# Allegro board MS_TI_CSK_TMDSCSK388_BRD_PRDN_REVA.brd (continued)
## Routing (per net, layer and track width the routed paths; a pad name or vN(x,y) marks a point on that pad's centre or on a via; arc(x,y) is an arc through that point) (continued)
DM388_GMII_RXER: length 37.2
  TOP w0.102: v1(40.52,25.41) 41.02,25.41 41.48,24.95 U7.AJ2
  L06_SIG2 w0.102: 38.94,25.41 v1(40.52,25.41)
  L06_SIG2 w0.119: v1(18.9,27.83) 18.3,28.42 16.36,28.42 16.24,28.54 16.24,28.9 16.36,29.02 25.78,29.02 26.17,29.41 27.87,29.41 28.72,30.26 33.3,30.26 33.42,30.14 33.42,29.78 33.54,29.67 33.78,29.67 33.9,29.78 33.9,30.14 34.02,30.26 35.83,30.26 37.07,29.02 37.07,28.65 36.95,28.53 36.79,28.53 36.7,28.44 36.7,28.12 36.82,28 37.36,28 37.6,27.77 37.6,26.7 38.88,25.41 38.94,25.41
  BOTTOM w0.14: 16.97,28.33 18.4,28.33 18.4,28.32 v1(18.9,27.83)
DM388_GMII_TXD[0]: length 23.5
  TOP w0.14: RA2.5 30.27,27.19 29.96,26.88 29.96,25.95 v1(30.04,25.87)
  L06_SIG2 w0.119: v1(18.98,21.18) 19.55,21.18 19.87,21.51 19.87,25.36 19.99,25.48 22.64,25.48 22.76,25.6 22.76,25.94 22.88,26.06 23.12,26.06 23.24,25.94 23.24,25.6 23.36,25.48 23.6,25.48 23.72,25.6 23.72,25.94 23.83,26.06 24.07,26.06 24.19,25.94 24.19,25.6 24.31,25.48 24.55,25.48 24.67,25.6 24.67,25.94 24.79,26.06 25.03,26.06 25.15,25.94 25.15,25.6 25.27,25.48 25.51,25.48 25.63,25.6 25.63,25.94 25.74,26.06 25.98,26.06 26.1,25.94 26.1,25.6 26.22,25.48 26.46,25.48 26.58,25.6 26.58,25.94 26.7,26.06 29.85,26.06 v1(30.04,25.87)
  BOTTOM w0.14: v1(18.98,21.18) 18.53,21.18 18.39,21.33 J4.17
DM388_GMII_TXD[1]: length 22.8
  TOP w0.14: v1(30.39,26.42) 30.55,26.42 30.67,26.54 RA2.6
  L06_SIG2 w0.119: v1(17.87,20.85) 18.77,21.76 19.43,21.76 19.6,21.93 19.6,25.57 19.44,25.73 18.82,25.73 18.69,25.86 18.69,26.07 18.81,26.19 19.93,26.19 20.04,26.07 20.04,25.92 20.16,25.8 20.4,25.8 20.52,25.92 20.52,26.24 20.64,26.36 20.88,26.36 21,26.24 21,25.92 21.12,25.8 21.36,25.8 21.48,25.92 21.48,26.24 21.6,26.36 21.84,26.36 21.95,26.24 21.95,25.92 22.07,25.8 22.31,25.8 22.43,25.92 22.43,26.24 22.55,26.36 28.57,26.36 28.63,26.42 v1(30.39,26.42)
  BOTTOM w0.14: J4.15 17.68,20.83 17.71,20.85 v1(17.87,20.85)
DM388_GMII_TXD[2]: length 24.3
  TOP w0.14: RA2.7 30.81,26.04 30.44,25.66 v1(30.44,25.16)
  L06_SIG2 w0.119: v1(30.44,25.16) 29.83,25.16 29.78,25.21 29.43,25.21 29.31,25.32 29.31,25.68 29.16,25.82 28.95,25.82 28.83,25.7 28.83,25.32 28.71,25.21 28.47,25.21 28.35,25.32 28.35,25.71 28.23,25.83 28,25.83 27.88,25.71 27.88,25.32 27.76,25.21 27.52,25.21 27.4,25.32 27.4,25.72 27.28,25.84 27.05,25.84 26.92,25.7 26.92,25.32 26.8,25.21 20.34,25.21 20.18,25.04 20.18,21.38 19.18,20.38 19.01,20.38 18.78,20.6 18.61,20.6 18.44,20.44 18.44,20.27 18.67,20.04 18.67,19.87 18.31,19.5 17.56,19.5 17.44,19.62 17.44,20.03 17.55,20.14 v1(17.81,20.14)
  BOTTOM w0.14: J4.13 17.52,20.33 17.71,20.14 v1(17.81,20.14)
DM388_GMII_TXD[3]: length 21
  TOP w0.102: v1(26.95,23.5) 27.21,23.75
  TOP w0.14: RA2.8 31.07,24.85 30.73,24.51 27.97,24.51 27.21,23.75
  L03_SIG1 w0.119: v1(17.86,19.11) 20.08,19.11 20.2,19.23 20.2,19.45 20.08,19.57 19.23,19.57 19.11,19.69 19.11,19.93 19.23,20.05 20.05,20.05 20.2,20.2 20.2,21.76 20.58,22.14 20.58,22.57 21.82,23.81 26.64,23.81 v1(26.95,23.5)
  BOTTOM w0.14: J4.9 17.51,18.83 17.78,19.1 17.85,19.1 v1(17.86,19.11)
DM388_GMII_TXD[4]: length 25.9
  TOP w0.14: RA3.5 34.1,27.19 33.73,26.82 33.73,26.24 33.09,25.6 32.93,25.6 v1(32.61,25.28)
  L06_SIG2 w0.119: v1(32.61,25.28) 32.17,25.28 32.11,25.21 32.11,24.87 31.93,24.7 31.55,24.7 31.43,24.82 31.43,25.52 31.31,25.64 31.07,25.64 30.95,25.52 30.95,24.82 30.83,24.7 29.74,24.7 29.5,24.93 20.63,24.93 20.45,24.76 20.45,21.19 19.62,20.36 19.62,20.15 v1(17.87,18.4)
  BOTTOM w0.14: J4.7 17.8,18.33 v1(17.87,18.4)
DM388_GMII_TXD[5]: length 24.6
  TOP w0.14: RA3.6 34.19,26.54 34.02,26.38 34.02,26.1 33.62,25.7 33.62,25.51 v1(33.59,25.48)
  L06_SIG2 w0.119: v1(17.86,17.69) 18.82,18.65 18.99,18.65 19.2,18.44 19.37,18.44 19.54,18.61 19.54,18.77 19.33,18.99 19.33,19.15 19.84,19.67 19.84,20.27 20.72,21.15 20.72,21.16 20.75,21.19 20.75,21.67 20.75,21.67 20.75,24.22 20.96,24.43 32.03,24.43 32.48,24.88 32.99,24.88 v1(33.59,25.48)
  BOTTOM w0.14: J4.5 17.64,17.83 17.78,17.69 v1(17.86,17.69)
DM388_GMII_TXD[6]: length 24.1
  TOP w0.14: v1(33.63,24.87) 34.05,25.28 34.05,25.72 34.37,26.04 RA3.7
  L06_SIG2 w0.102: 21.11,23.63 21.23,23.75
  L06_SIG2 w0.119: 21.11,23.63 21.02,23.54 21.02,21.56 21.02,21.55 21.02,21.07 21,21.05 21,21.04 20.48,20.52 20.48,19.14 18.3,16.97 v1(17.86,16.97) ; 21.23,23.75 21.64,24.16 32.26,24.16 32.66,24.56 33.32,24.56 v1(33.63,24.87)
  BOTTOM w0.14: v1(17.86,16.97) 17.84,16.97 17.48,17.33 J4.3
DM388_GMII_TXD[7]: length 24.8
  TOP w0.14: v1(34.32,24.94) 34.32,25.08 RA3.8
  L06_SIG2 w0.119: v1(34.32,24.94) 34.01,24.63 34.01,24.58 33.71,24.28 32.87,24.28 32.47,23.89 21.76,23.89 21.29,23.42 21.29,21.44 21.29,21.44 21.29,20.9 20.89,20.49 20.89,18.55 18.39,16.05 v1(17.89,16.05)
  BOTTOM w0.14: v1(17.89,16.05) 17.31,16.05 16.97,16.39 J4.1
DM388_GMII_TXEN: length 29.5
  L03_SIG1 w0.119: v1(17.9,23.73) 16.67,23.73 15.61,22.67 15.61,21.87 15.73,21.75 16.99,21.75 17.12,21.88 17.12,23.07 17.27,23.22 18.98,23.22 20.46,24.7 28.34,24.7 28.94,24.1 29.8,24.1 31.36,24.1 31.39,24.13 35.61,24.13 35.87,23.88 v1(36.39,23.88)
  BOTTOM w0.14: v1(36.39,23.88) 36.71,23.56 36.92,23.56 37.12,23.37 37.12,23.07 37.59,22.59 R114.1 ; v1(17.9,23.73) 17.8,23.83 J4.27
DM388_GP0[9]: length 53.9
  TOP w0.102: U7.AG30 42.48,9.46 42.49,9.44 42.49,7.85 42.43,7.79
  TOP w0.14: 42.43,7.79 42.43,6.85 42.63,6.66 v1(42.63,6.21)
  L06_SIG2 w0.102: 57.31,15.65 55.68,15.65 54.89,14.86 54.49,14.86 53.55,13.92 50.37,13.92 50.21,13.76 49.76,13.76 49.53,13.52 49.53,13.1 49.58,13.04 49.58,10.05 50.04,9.59 50.17,9.59 51.97,7.79
  L06_SIG2 w0.119: v1(61.89,23.66) 62.2,23.35 62.2,20.32 57.53,15.65 57.31,15.65 ; 51.97,7.79 52.71,7.05 52.71,5.21 52.28,4.78 44.09,4.78 43.45,5.43 43.45,5.85 43.09,6.21 v1(42.63,6.21)
  BOTTOM w0.14: 67.75,28.23 66.57,28.23 65.87,28.93 63.68,28.93 62.67,27.92 62.67,26.77 61.89,26 v1(61.89,23.66)
DM388_GP1[10]: length 35.7
  TOP w0.102: v1(41.36,26.57) 41.66,26.26 41.66,26.21 41.74,26.14 42.12,26.14 42.48,25.78 U7.AG1
  L06_SIG2 w0.102: 41.36,26.59 v1(41.36,26.57)
  L06_SIG2 w0.119: 41.36,26.59 41.36,27.75 36.85,32.25 36.84,32.25 35.89,33.2 34.76,33.2 33.42,34.54 27.59,34.54 26.95,33.91 24.48,33.91 23.69,34.69 19.31,34.69 19.11,34.48 18.7,34.48 18.41,34.77 18.41,35.06 18.06,35.41 17.69,35.41 17.45,35.65 17.45,36.02 18.18,36.75 v1(18.62,36.75)
  BOTTOM w0.14: J4.75 18.1,36.83 18.17,36.75 v1(18.62,36.75)
DM388_GP1[14]: length 68.5
  TOP w0.102: v1(49.48,22.05) 49.69,22.05 U7.M5
  L06_SIG2 w0.102: v1(49.48,22.05) 49.48,21.53 49.21,21.25 49.21,20.92 49.4,20.72 49.4,19.91 49.15,19.66 49.11,19.66 48.95,19.5 48.28,19.5 48.05,19.72 48.05,23.52 48.88,24.34 51.76,24.34 51.9,24.2 53.11,24.2 54.38,25.47 54.38,25.78 54.16,26.01 53.84,26.01 53.57,25.73 52.12,25.73 51.62,25.22 50.25,25.22 49.31,26.16 44.41,26.16 43.98,26.59
  L06_SIG2 w0.119: v1(14.89,36.2) 15.33,36.2 16.85,37.71 19.16,37.71 19.79,37.08 20.2,37.08 20.37,37.26 22.11,37.26 22.12,37.26 23.51,37.26 23.56,37.31 32.05,37.31 32.38,36.98 33.76,36.98 35.16,35.58 36.89,35.58 38.19,34.28 41.22,34.28 41.34,34.17 41.59,34.17 43.33,32.43 43.33,31.39 43.54,31.18 43.54,27.03 43.98,26.59
  BOTTOM w0.14: v1(14.89,36.2) 14.86,36.22 14.6,36.22 14.5,36.33 J4.74
DM388_GP1[24]: length 39.2
  TOP w0.102: U7.AA12 v1(45.48,19.25)
  L06_SIG2 w0.102: 41.93,26.59 41.95,26.59 44.43,24.12 44.43,20.42 45.17,19.68 45.17,19.56 v1(45.48,19.25)
  L06_SIG2 w0.119: 41.93,26.59 41.79,26.73 41.79,27.62 36.95,32.47 36.93,32.47 35.91,33.49 34.94,33.49 33.67,34.77 27.43,34.77 26.84,34.18 24.59,34.18 23.73,35.04 19.54,35.04 v1(18.75,35.83)
  BOTTOM w0.14: J4.69 18.25,35.33 v1(18.75,35.83)
DM388_GP1[25]: length 35.4
  TOP w0.102: U7.AC3 44.86,23.34 v1(44.93,23.27)
  L06_SIG2 w0.102: 42.27,26.59 44.93,23.93 v1(44.93,23.27)
  L06_SIG2 w0.119: 36.74,32.97 35.95,33.77 35.17,33.77 33.95,34.99 27.27,34.99 26.76,34.48 25.86,34.48 24.93,35.4 19.77,35.4 18.92,36.24 18.28,36.24 v1(17.86,35.83) ; 36.74,32.97 36.81,32.9 ; 36.74,32.97 36.81,32.91 ; 36.81,32.9 37.03,32.69 37.04,32.69 42.07,27.66 42.07,26.8 42.27,26.59
  BOTTOM w0.14: J4.71 v1(17.86,35.83)
DM388_GP1[30]: length 52.1
  TOP w0.102: v1(45.95,18.87) 45.98,18.9 U7.Y11
  L03_SIG1 w0.102: v1(45.95,18.87) 45.95,19.34 45.52,19.76 45.09,19.76 43.77,21.08 39.38,21.08 39.23,21.24 38.94,21.24
  L03_SIG1 w0.119: v1(19.21,22.2) 19.82,22.2 21.62,24 21.7,24 21.73,24.03 27.4,24.03 27.91,23.52 27.91,23.5 28.46,22.95 31.69,22.95 31.92,22.71 31.92,22.39 32.15,22.16 32.68,22.16 32.69,22.16 34.96,22.16 35.88,21.24 38.94,21.24
  L06_SIG2 w0.119: v1(19.21,22.2) 19.21,24.78 18.21,25.78 17.31,25.78 16.88,26.21 16.88,26.76 15.28,28.36 13.74,28.36 13.04,29.07 13.04,33.24 13.48,33.68 13.68,33.68 14.32,34.32 15.23,34.32 15.79,34.88 v1(17.89,34.88)
  BOTTOM w0.14: J4.67 17.84,34.83 v1(17.89,34.88)
DM388_GP3[3]: length 45.2
  TOP w0.102: v1(52.3,25.02) 52,24.71 52,24.66 51.97,24.64 51.97,24.34 U7.G2
  L06_SIG2 w0.102: v1(52.3,25.02) 51.87,25.02 51.8,24.95 49.45,24.95 48.8,25.6 44.63,25.6 43.64,26.59
  L06_SIG2 w0.119: 43.64,26.59 43.23,27.01 43.23,31.11 43.06,31.28 43.06,32.31 41.84,33.54 41.66,33.54 41.13,34.06 37.94,34.06 36.77,35.23 35.09,35.23 33.72,36.6 33.59,36.71 25.07,36.71 24.74,37.04 22.21,37.04 22,36.83 v1(21.29,36.83)
  BOTTOM w0.14: J4.73 19.74,36.33 20.24,36.83 v1(21.29,36.83)
DM388_GP3[4]: length 97
  TOP w0.102: v1(51.23,23.25) 51.89,23.25 U7.H3
  L03_SIG1 w0.119: v1(18.63,22.82) 18.59,22.78 18.59,22.65 18.24,22.3 18.02,22.3 17.16,21.45 12.85,21.45 11.34,19.94 9.21,19.94 8.23,20.92 8.22,20.92 8.22,21.96 v1(8.92,22.66)
  L06_SIG2 w0.102: 56.61,26.59 56.61,26.39 53.6,23.38 51.78,23.38 51.66,23.25 v1(51.23,23.25)
  L06_SIG2 w0.119: 56.61,26.59 56.61,28.48 56.1,28.99 56.1,30.92 55.37,31.65 55.12,31.65 54.84,31.92 54.84,31.96 54.81,32 54.81,32.32 54.84,32.35 54.84,33.69 54.02,34.51 54.02,35.19 53.02,36.19 50.47,36.19 49.8,35.53 49.8,35.5 49.53,35.23 44.05,35.23 42.98,36.29 41.63,36.29 39.67,38.25 33.48,38.25 31.21,40.52 23.76,40.52 22.32,39.08 12.84,39.08 10.86,37.1 10.86,23.65 9.87,22.66 v1(8.92,22.66)
  BOTTOM w0.14: J4.21 17.81,22.33 17.81,22.32 18.23,22.32 18.52,22.62 18.52,22.63 18.59,22.7 18.59,22.78 v1(18.63,22.82)
DM388_GPMC_ALE: length 26.6
  TOP w0.102: U7.AA10 45.48,20.26 v1(45.44,20.3)
  L03_SIG1 w0.102: v1(45.44,20.3) 44.88,20.3 44.45,20.73 44.45,23.72 45.55,24.82 46.29,24.82 48.07,26.59
  L03_SIG1 w0.119: v1(49.53,33.09) 49.53,31.91 49.66,31.77 49.66,30.25 50.27,29.64 50.27,28.62 49.5,27.84 49.32,27.84 48.07,26.59
  BOTTOM w0.14: U13.17 55.76,36.96 55.55,36.75 54.53,36.75 54.23,36.45 52.58,36.45 51,34.87 51,34.56 v1(49.53,33.09)
DM388_GPMC_CLE: length 23.3
  TOP w0.102: U7.Y3 45.51,23.34 v1(45.49,23.32)
  L03_SIG1 w0.102: 48.46,26.59 45.8,23.94 45.8,23.63 v1(45.49,23.32)
  L03_SIG1 w0.119: 48.46,26.59 49.43,27.57 49.61,27.57 50.06,28.03 50.06,28.1 50.49,28.53 50.49,29.73 50,30.23 50,32.13 49.82,32.31 49.82,32.64 50,32.82 50,33.27 49.77,33.5 49.67,33.5 v1(49.36,33.81)
  BOTTOM w0.14: U13.16 55.61,37.46 55.3,37.77 53.32,37.77 v1(49.36,33.81)
DM388_GPMC_CS[0]N: length 53.6
  TOP w0.102: U7.AC9 v1(44.48,19.84)
  L03_SIG1 w0.119: v1(31.28,33.88) 40.24,42.85 v1(46.71,42.85)
  L06_SIG2 w0.102: 40.94,26.59 40.94,26.45 40.97,26.42 40.97,26.41 41.2,26.19 41.2,26.19 41.25,26.14 42.12,26.14 44.07,24.19 44.07,20.24 v1(44.48,19.84)
  L06_SIG2 w0.119: v1(31.28,33.88) 32.49,32.67 36.11,32.67 36.75,32.03 36.76,32.03 40.94,27.85 40.94,26.59 ; v1(46.71,42.85) 47.81,42.85 48.29,43.33 50.64,43.33 51.26,42.71 52.34,42.71 v1(54.46,40.59)
  BOTTOM w0.14: U13.9 55.9,40.96 55.53,40.59 v1(54.46,40.59)
DM388_GPMC_OEN_REN: length 36.5
  TOP w0.102: U7.Y8 45.98,20.94 45.49,21.43 v1(45.49,21.48)
  L03_SIG1 w0.102: v1(45.49,21.48) 45.86,21.48 46.26,21.88 46.26,23.63 49.23,26.59
  L03_SIG1 w0.119: v1(46.48,36.93) 46.17,36.62 46.17,35.55 47.44,34.27 49.56,34.27 50.6,33.24 50.6,30.25 50.93,29.92 50.93,28.34 50.61,28.02 50.61,27.8 50.45,27.64 49.83,27.03 49.66,27.03 49.23,26.59
  BOTTOM w0.14: v1(46.48,36.93) 46.48,36.28 46.84,35.92 48.69,35.92 50.32,37.55 50.32,38.58 53.2,41.46 U13.8
DM388_GPMC_WAIT0: length 37.7
  TOP w0.102: v1(46,20.38) 46.46,20.84 U7.W8
  TOP w0.14: v1(55.86,41.96) 56.41,41.41 R20.2
  L06_SIG2 w0.102: v1(46,20.38) 46.26,20.38 46.43,20.2 46.43,19.64 46.92,19.15 48.89,19.15 49.19,19.46 49.41,19.46 51.03,21.08 51.2,21.08 54.52,21.08 56.67,23.23
  L06_SIG2 w0.119: v1(55.86,41.96) 55.86,40.04 55.48,39.66 55.48,39.26 56.26,38.47 56.26,36.98 58.96,34.29 58.96,32.31 58.6,31.96 58.6,28.86 57.7,27.96 57.7,26.46 56.67,25.43 56.67,23.23
  BOTTOM w0.14: U13.7 v1(55.86,41.96)
DM388_GPMC_WEN: length 22.1
  TOP w0.102: v1(45.48,22.06) 45.76,22.34 U7.Y5
  L03_SIG1 w0.102: 48.84,26.59 46.05,23.81 46.05,22.63 v1(45.48,22.06)
  L03_SIG1 w0.119: 48.84,26.59 49.55,27.3 49.72,27.3 50.34,27.92 50.34,28.06 50.71,28.44 50.71,29.83 50.27,30.27 50.27,32.24 50.21,32.31 v1(50.21,32.47)
  BOTTOM w0.14: U13.18 56.13,36.46 56.07,36.41 54.67,36.41 53.13,34.87 52.43,34.87 50.53,32.96 50.53,32.79 v1(50.21,32.47)
DM388_GPMC_WPN: length 32.9
  TOP w0.102: 42.56,26.59 42.56,26.29 42.96,25.89 42.96,25.88 42.98,25.86 U7.AF2
  TOP w0.14: v1(40.33,32.59) 40.33,31.43 41.74,30.02 41.74,27.59 42.56,26.76 42.56,26.59 ; R35.2 57.01,37.74 56.18,36.91 56.18,36.21 v1(55.87,35.89)
  BOTTOM w0.14: v1(40.33,32.59) 40.85,32.06 41.52,32.06 41.88,32.42 45.79,32.42 46.36,33 46.36,33.15 46.92,33.72 48.66,33.72 48.99,33.39 48.99,32.65 49.57,32.07 50.7,32.07 52.81,34.19 52.87,34.19 54.82,36.14 55.16,36.14 55.41,35.89 v1(55.87,35.89) 55.89,35.89 55.96,35.96 U13.19
DM388_HDMI_CEC: length 83.9
  TOP w0.102: v1(51.11,25.81) 50.77,25.46 50.53,25.46 50.29,25.22 49.97,25.22 49.2,24.45 49.2,24.22 49.21,24.21 49.21,24.11 U7.N2
  L06_SIG2 w0.102: 55.35,26.5 55.07,26.21 54.16,26.21 53.88,26.49 51.79,26.49 v1(51.11,25.81)
  L06_SIG2 w0.119: v1(14.46,18.31) 14.14,18.63 13.6,18.63 13.57,18.59 12.88,18.59 11.97,19.51 11.97,24.16 11.41,24.72 11.41,36.88 12.93,38.41 20.48,38.41 20.63,38.25 31.88,38.25 32.47,37.67 36.17,37.67 39.08,34.76 41.85,34.76 42.52,34.09 43.52,34.09 46.23,31.37 49.84,31.37 50.19,31.02 53.41,31.02 53.78,30.66 53.78,29.25 54.01,29.02 54.61,29.02 55.48,28.14 55.48,26.63 55.35,26.5
  BOTTOM w0.14: v1(14.46,18.31) 14.14,18 14.14,17.69 13.97,17.53 13.42,17.53 13.12,17.83 J4.6
DM388_HDMI_CLKN: length 49.4
  TOP w0.102: U7.B15 55.25,17.06 56.73,17.06 57.03,16.76 64.94,16.76 69.02,20.84 69.02,26.59 69.37,26.95 71.19,26.95 72.83,28.59 72.83,38.98 71.49,40.31 69.44,40.31 67.89,41.86 65.89,41.86 65.46,41.43 65.46,40.96 v1(65.23,40.74)
  BOTTOM w0.102: v1(65.23,40.74) 65.46,40.96 65.46,41.23 65.84,41.62 66.96,41.62 67.07,41.73 J3.2
DM388_HDMI_CLKP: length 49.4
  TOP w0.102: v1(66.2,40.74) 66.2,40.35 66.09,40.25 65.84,40.25 65.74,40.35 65.74,41.31 66.01,41.58 67.77,41.58 69.32,40.03 71.38,40.03 72.55,38.86 72.55,28.7 71.07,27.23 69.26,27.23 68.74,26.71 68.74,20.96 64.82,17.04 57.14,17.04 56.85,17.34 U7.A15
  BOTTOM w0.102: J3.4 67.07,41.23 66.96,41.34 65.96,41.34 65.74,41.12 65.74,40.34 65.84,40.24 66.09,40.24 66.2,40.34 v1(66.2,40.74)
DM388_HDMI_DN0: length 38.9
  TOP w0.102: v1(70.61,39.25) 70.39,39.03 70.39,38.85 70.63,38.61 71.38,38.61 72.01,37.97 72.01,29.15 70.73,27.86 69.12,27.86 68.23,26.98 68.23,22.35 63.4,17.53 57.19,17.53 57.15,17.57 55.75,17.57 U7.A14
  BOTTOM w0.102: J3.8 68.43,40.23 68.54,40.12 70,40.12 70.29,39.83 70.29,39.52 70.56,39.25 v1(70.61,39.25)
DM388_HDMI_DN1: length 35.9
  TOP w0.102: v1(70.81,37.24) 70.62,37.24 70.57,37.19 70.57,36.96 71.23,36.3 71.23,33.73 70.62,33.12 68.74,33.12 68.63,33.02 68.63,28.91 67.44,27.71 67.44,22.69 63.01,18.26 57.89,18.26 57.65,18.02 56.61,18.02 56.32,18.31 55.68,18.31 55.68,18.32 54.99,18.32 U7.B13
  BOTTOM w0.102: J3.14 68.43,38.23 68.54,38.12 70,38.12 70.41,37.7 70.41,37.32 70.5,37.24 v1(70.81,37.24)
DM388_HDMI_DN2: length 31.5
  TOP w0.102: v1(70.29,35.93) 70.16,35.81 70.16,34.9 70.06,34.8 68.62,34.8 67.75,33.92 67.75,29.34 66.65,28.25 66.65,25.93 64.55,23.83 64.55,20.94 62.6,19 57.94,19 57.74,19.2 57.01,19.2 56.58,18.77 55.83,18.77 55.76,18.84 U7.A12
  BOTTOM w0.102: J3.20 68.43,36.73 68.54,36.62 70.03,36.62 70.29,36.36 v1(70.29,35.93)
DM388_HDMI_DP0: length 39
  TOP w0.102: U7.B14 55.25,18.12 55.59,18.12 55.91,17.81 63.29,17.81 67.95,22.47 67.95,27.09 69,28.14 70.62,28.14 71.73,29.26 71.73,37.86 71.26,38.33 70.51,38.33 70.11,38.74 70.11,39.12 69.97,39.25 v1(69.64,39.25)
  BOTTOM w0.102: J3.10 68.43,39.73 68.54,39.84 69.88,39.84 70.01,39.71 70.01,39.52 69.73,39.25 v1(69.64,39.25)
DM388_HDMI_DP1: length 36
  TOP w0.102: v1(69.85,37.24) 69.85,37.48 70.1,37.73 70.2,37.73 70.29,37.64 70.29,36.84 70.95,36.18 70.95,33.85 70.5,33.4 68.62,33.4 68.36,33.14 68.36,29.02 67.16,27.83 67.16,22.81 62.89,18.54 57.78,18.54 57.54,18.3 56.62,18.3 56.4,18.52 55.77,18.52 55.76,18.53 55.29,18.53 U7.B12
  BOTTOM w0.102: v1(69.85,37.24) 69.98,37.24 70.14,37.39 70.14,37.58 69.88,37.84 68.54,37.84 68.43,37.73 J3.16
DM388_HDMI_DP2: length 31.5
  TOP w0.102: v1(69.68,35.39) 69.36,35.08 68.85,35.08 68.51,35.08 67.47,34.04 67.47,33.81 67.47,29.45 66.37,28.36 66.37,26.05 64.27,23.94 64.27,21.06 63.65,20.44 63.64,20.44 63.58,20.38 63.58,20.37 62.49,19.28 58.05,19.28 57.85,19.48 57.01,19.48 56.5,18.97 55.91,18.97 55.55,19.34 U7.A11
  BOTTOM w0.102: v1(69.68,35.39) 69.68,34.96 69.77,34.87 70.01,34.87 70.11,34.97 70.11,35.54 69.88,35.76 69.88,36.12 69.66,36.34 68.54,36.34 68.43,36.23 J3.22
DM388_HDMI_HPDET: length 87.5
  TOP w0.102: v1(48.95,20.62) 48.63,20.62 48.48,20.77 U7.R8
  L06_SIG2 w0.102: 55.76,26.59 55.76,26.55 53.2,24 51.81,24 51.73,24.08 48.91,24.08 48.36,23.53 48.36,21.21 v1(48.95,20.62)
  L06_SIG2 w0.119: 55.76,26.59 55.76,26.71 55.8,26.75 55.8,28.16 55.43,28.53 55.43,29.41 55.2,29.64 54.92,29.64 54.49,30.07 54.49,30.33 53.53,31.29 52.61,31.29 49.54,34.36 42.64,34.36 41.95,35.04 39.4,35.04 36.47,37.97 32.93,37.97 31.55,39.35 26.17,39.35 25.57,38.76 12.9,38.76 11.13,36.99 11.13,19.78 10.11,18.76 9.33,18.76 v1(9.02,19.08)
  BOTTOM w0.14: J4.8 9.77,18.33 v1(9.02,19.08)
DM388_HDMI_SCL: length 69
  TOP w0.102: v1(53.31,25.06) 53.69,24.68 53.69,24.15 53.98,23.86 U7.D2
  TOP w0.14: R67.2 18.37,25.88 18.6,25.65 v1(18.6,24.8)
  L06_SIG2 w0.102: 42.92,26.59 44.32,25.2 48.29,25.2 48.95,24.54 51.84,24.54 51.94,24.44 52.05,24.44 52.06,24.43 52.54,24.43 52.55,24.44 52.6,24.44 52.61,24.45 52.69,24.45 v1(53.31,25.06)
  L06_SIG2 w0.119: 42.92,26.59 42.63,26.88 42.63,28.45 42.45,28.63 42.45,32.12 41.55,33.02 38.3,33.02 36.67,34.65 34.78,34.65 33.36,36.07 27.84,36.07 27.31,35.54 25.43,35.54 25.3,35.67 20.26,35.67 18.76,37.17 17.68,37.17 15.08,34.57 14.26,34.57 13.59,33.9 13.31,33.9 12.77,33.35 12.77,28.96 13.63,28.09 15.16,28.09 16.61,26.65 16.61,25.89 17,25.5 17.91,25.5 v1(18.6,24.8)
  BOTTOM w0.14: v1(18.6,24.8) 18.17,24.36 18.13,24.33 J4.29
DM388_HDMI_SDA: length 67.4
  TOP w0.102: v1(54,25.63) 54,25.24 53.98,25.22 U7.D1
  TOP w0.14: R70.2 17.93,24.84 v1(17.94,24.85)
  L06_SIG2 w0.102: v1(54,25.63) 53.9,25.53 53.24,25.53 52.68,24.97 52.68,24.81 52.52,24.64 52.47,24.64 52.46,24.64 52.14,24.64 52.14,24.64 52.03,24.64 51.92,24.75 49.21,24.75 48.55,25.4 44.48,25.4 43.29,26.59
  L06_SIG2 w0.119: v1(17.94,24.85) 17.62,25.16 16.96,25.16 16.33,25.78 16.33,26.54 15.05,27.82 13.52,27.82 12.49,28.85 12.49,33.46 13.15,34.12 13.5,34.12 14.23,34.85 14.97,34.85 17.56,37.44 18.8,37.44 20.3,35.94 24.72,35.94 25.19,36.42 33.41,36.42 34.9,34.93 36.7,34.93 37.79,33.84 41.04,33.84 41.66,33.23 41.73,33.23 42.72,32.23 42.72,32.18 42.73,32.18 42.73,28.73 42.95,28.51 42.95,26.93 43.29,26.59
  BOTTOM w0.14: v1(17.94,24.85) 17.91,24.83 J4.31
DM388_I2C0_SCL: length 115.1
  TOP w0.102: U1.M4 v1(37.46,49.82) ; U7.T27 48.11,11.34 48.43,11.03 v1(48.44,11.03)
  L03_SIG1 w0.102: v1(49.83,9.01) 56.05,9.01 56.35,9.31 57.31,9.31
  L03_SIG1 w0.119: v1(37.46,49.82) 37.46,50.89 37.9,51.33 37.9,54.46 40.34,56.9 42.02,56.9 42.42,56.49 46.05,56.49 51.27,51.27 62.63,51.27 64.47,49.43 66.62,49.43 67.42,48.63 67.42,45.04 68.25,44.2 73.84,44.2 76.69,41.35 76.69,38.88 v1(77,38.56) ; 57.31,9.31 58.18,9.31 58.5,8.99 59.1,8.99 59.41,8.68 60.18,8.68 60.74,8.12 66.06,8.12 69.14,11.2 v1(70.46,11.2)
  L06_SIG2 w0.102: v1(48.44,11.03) 48.02,10.6 48.02,9.91 48.92,9.01 v1(49.83,9.01)
  BOTTOM w0.14: v1(77,38.56) 76.07,37.62 76.07,28.45 76.09,28.42 76.09,28.35 76.51,27.93 76.51,23.13 76.43,23.05 76.43,18.65 75.61,17.83 75.61,16.35 v1(70.46,11.2) ; R95.2 37.91,50.27 v1(37.46,49.82)
DM388_I2C0_SDA: length 117.6
  TOP w0.102: U7.T24 48.04,12.84 48.41,12.47 48.41,12.38 v1(48.43,12.36) ; U1.M5 v1(37.04,50.47)
  L03_SIG1 w0.102: v1(49.74,8.46) 50.37,8.46 50.68,8.76 56.1,8.76 56.37,9.04 57.31,9.04
  L03_SIG1 w0.119: v1(37.04,50.47) 37.04,50.93 37.62,51.51 37.62,54.59 40.19,57.15 42.13,57.15 42.4,56.88 46.05,56.88 51.43,51.49 62.77,51.49 64.6,49.66 66.7,49.66 67.66,48.7 67.66,45.15 68.36,44.45 73.9,44.45 77,41.35 77,39.41 77.55,38.86 v1(77.55,37.85) ; 57.31,9.04 58.07,9.04 58.39,8.72 58.99,8.72 59.3,8.41 60.1,8.41 60.66,7.85 66.17,7.85 68.76,10.44 v1(70.13,10.44)
  L06_SIG2 w0.102: v1(49.74,8.46) 49.18,8.46 47.82,9.83 47.82,11.74 v1(48.43,12.36)
  BOTTOM w0.14: v1(70.13,10.44) 70.58,10.44 73.23,13.09 73.23,13.62 75.85,16.23 75.85,17.73 76.67,18.55 76.67,22.95 76.76,23.03 76.76,28.1 76.31,28.55 76.31,36.61 v1(77.55,37.85) ; R96.2 37.02,50.88 37.04,50.86 v1(37.04,50.47)
DM388_I2C2_SCL: length 73
  TOP w0.102: U7.E31 53.75,9.07 53.75,9.04 54.41,8.38 v1(54.84,8.38) 55.43,7.79
  TOP w0.14: v1(56.82,3.17) 58.61,3.17 59.62,4.18 59.62,6.94 59.19,7.37 57.88,7.37 57.53,7.71 55.51,7.71 55.43,7.79
  L06_SIG2 w0.119: v1(56.82,3.17) 56.38,3.17 55.67,3.89 41.31,3.89 41.09,3.66 39.81,3.66 37.95,1.81 18.53,1.81 15.21,5.13 15.21,15.55 14.24,16.51 v1(13.64,16.51)
  BOTTOM w0.102: R130.2 55.42,8.13 55.15,8.13 54.89,8.38 v1(54.84,8.38)
  BOTTOM w0.14: J4.2 13.33,16.83 v1(13.64,16.51)
DM388_I2C2_SDA: length 68.9
  TOP w0.102: U7.E29 53.83,10.34 v1(54.01,10.52)
  L06_SIG2 w0.102: 53.57,7.79 53.57,8.79 52.56,9.81 52.56,11.02 52.78,11.24 53.19,11.24 53.71,10.72 53.8,10.72 v1(54.01,10.52)
  L06_SIG2 w0.119: 53.57,7.79 53.57,4.91 52.82,4.17 41.28,4.17 41,3.89 39.65,3.89 37.84,2.08 18.65,2.08 15.48,5.24 15.48,15.66 14.13,17.01 10.27,17.01 v1(9.95,17.33)
  BOTTOM w0.102: v1(54.01,10.52) 54.31,10.82 54.62,10.82 54.85,10.59 55.11,10.59 R121.2
  BOTTOM w0.14: J4.4 v1(9.95,17.33)
DM388_MCA[1]_AHCLKX: length 54.7
  L06_SIG2 w0.119: v1(74.72,19.73) 75.46,19.73 77.48,17.7 77.48,15.2 66.15,3.86 59.69,3.86 58.29,2.46 56.01,2.46 55.39,3.07 43.52,3.07 41.71,1.26 v1(41.71,0.82)
  BOTTOM w0.14: v1(41.71,0.82) 40.86,0.82 40.03,1.65 R139.2 ; v1(74.72,19.73) 74.2,19.73 73.7,20.23 J3.79
DM388_MCASP0_ACLKR: length 68.4
  L03_SIG1 w0.119: v1(66.36,19.66) 66.36,20.31 66.66,20.61 68.59,20.61 68.88,20.89 68.88,22.5 69.68,23.29 70.29,23.29 70.48,23.11 70.72,22.86 70.72,22.86 70.9,22.67 73.31,22.67 73.81,23.17 75.68,23.17 76.6,22.25 v1(77.58,22.25)
  L06_SIG2 w0.119: v1(47.27,1.14) 47.58,1.46 48.09,1.46 48.12,1.49 48.68,1.49 49.05,1.12 65.23,1.12 78.77,14.66 78.77,21.06 v1(77.58,22.25)
  BOTTOM w0.14: v1(66.36,19.66) 66.04,19.98 66.04,20.02 64.79,21.27 J5.23 ; v1(47.27,1.14) 47.27,1.26 47.14,1.39 47.14,1.55 46.4,2.3 44.69,2.3 43.84,3.15 R137.2
DM388_MCASP0_ACLKX: length 84.8
  TOP w0.14: R52.1 v1(66.4,34.24)
  L06_SIG2 w0.119: v1(66.4,34.24) 66.88,34.24 67.54,34.9 71.9,34.9 73.14,36.14 73.49,36.14 73.73,35.9 73.73,35.61 74.1,35.24 75.21,35.24 78.32,32.13 78.32,24.3 77.17,23.14 77.17,21.28 78.13,20.32 78.13,14.93 64.96,1.76 49.32,1.76 48.95,2.13 44.48,2.13 v1(43.13,0.79)
  BOTTOM w0.102: 42.97,7.79 42.97,7.81 43.43,8.27 R127.2
  BOTTOM w0.14: 42.97,7.79 42.97,7.15 42.13,6.32 42.13,5.79 41.76,5.42 41.76,3.99 40.92,3.14 40.92,2.81 40.9,2.79 40.9,1.86 41.06,1.7 42.68,1.7 43.13,1.24 v1(43.13,0.79)
DM388_MCASP0_AFSR: length 55.6
  TOP w0.102: U7.AF30 42.7,9.56 42.7,9.22 42.72,9.2 42.72,7.79
  TOP w0.14: v1(43.06,5.69) 43.06,6.68 42.72,7.01 42.72,7.79
  L06_SIG2 w0.102: 53.3,7.79 53.3,8.7 52.3,9.7 52.3,11.13 52.65,11.48 53.72,11.48 53.83,11.58 54.16,11.58 54.99,10.75 54.99,9.86 55.66,9.2 57.31,9.2
  L06_SIG2 w0.119: 57.31,9.2 58.9,9.2 59.41,8.68 60,8.68 60.87,7.81 64.73,7.81 68.01,11.09 69.05,11.09 70.06,12.1 70.06,12.96 69.96,13.06 69.96,13.46 v1(69.6,13.82) ; 53.3,7.79 53.3,5.03 52.71,4.43 43.82,4.43 43.06,5.2 v1(43.06,5.69)
  BOTTOM w0.14: v1(69.6,13.82) 68.69,14.73 68.69,16.21 66.25,18.64 66.25,19.11 64.59,20.77 J5.25
DM388_MCASP0_AFSX: length 41.1
  TOP w0.102: v1(42.81,10.84) 42.82,10.85 42.92,10.85 43.43,10.34 U7.AE29
  TOP w0.14: R41.1 66.09,35.26 66.82,34.53 66.82,34.06 66.81,34.04 66.81,31.92 66.55,31.66 66.5,31.66 v1(66.18,31.35)
  L06_SIG2 w0.102: v1(42.81,10.84) 43.56,11.6 43.56,12.83 45.39,14.65 45.39,15.22 45.39,15.22 45.39,15.52 45.35,15.56 45.35,17.6 45.72,17.96 46.13,17.96 47.04,18.87 48.89,18.87 49.27,19.25 49.49,19.25 50.94,20.7 54.51,20.7
  L06_SIG2 w0.119: v1(66.18,31.35) 65.83,30.99 63.02,30.99 57.81,25.78 57.81,25.34 57.09,24.61 57.09,23.27 54.51,20.7
DM388_MCASP0_AXR0: length 43.9
  TOP w0.102: v1(42.46,10.36) 42.48,10.34 U7.AF29
  TOP w0.14: v1(66.2,36.75) 65.8,36.36 R38.1
  L06_SIG2 w0.102: 54.64,20.32 51.83,20.32 50.4,18.88 50.4,18.71 49.97,18.29 49.57,18.29 49.03,17.76 45.8,17.76 45.56,17.51 45.56,15.64 45.59,15.61 45.59,14.57 43.77,12.74 43.77,11.23 42.89,10.36 v1(42.46,10.36)
  L06_SIG2 w0.119: v1(66.2,36.75) 65.76,36.32 65.76,32.59 66.57,31.78 66.57,31.18 66.13,30.73 63.08,30.73 58.06,25.71 58.06,25.27 57.31,24.52 57.31,22.99 54.64,20.32
DM388_MCASP0_AXR1: length 122.3
  TOP w0.102: U7.AE31 43.52,9.3 43.52,7.79
  TOP w0.14: v1(43.52,7.54) 43.52,7.79
  L06_SIG2 w0.102: 39.55,46.48 36.39,46.48 35.55,47.32 32.8,47.32 31.96,46.48 29.35,46.48 29.17,46.3
  L06_SIG2 w0.119: v1(43.52,7.54) 42.7,7.54 41.56,6.41 41.56,6.06 41.19,5.69 39.78,5.69 39.19,5.1 39.19,3.99 37.55,2.35 18.76,2.35 15.75,5.36 15.75,15.77 14.41,17.12 14.41,17.83 14.31,17.92 14.29,17.92 13.85,18.37 9.14,18.37 7.77,19.73 7.77,24.11 8.94,25.28 8.94,26.02 8.81,26.16 8.81,27.45 9.66,28.3 9.66,30.81 8.94,31.52 8.94,34.32 9.65,35.02 9.65,37.84 11.59,39.78 15.55,39.78 17.68,41.91 21.24,41.91 22.64,43.31 26.17,43.31 29.17,46.3 ; 39.55,46.48 45.19,46.48 45.91,47.2 45.91,49.3 42.88,52.33 v1(42.88,52.77)
  BOTTOM w0.14: R90.1 43.01,52.91 42.88,52.78 v1(42.88,52.77)
DM388_MCASP0_AXR2: length 67.2
  TOP w0.102: U7.AE30 43.77,9.54 43.77,8.91 43.9,8.78 43.9,6.25 43.72,6.07 43.72,5.78 43.72,5.78 43.72,5.45 43.72,5.41 44,5.13 44.39,5.13 44.71,4.81 44.71,2.79 44.54,2.62 v1(44.54,0.84)
  L03_SIG1 w0.119: v1(8.38,19.79) 8.38,18.03 9.07,17.34 9.07,10.25 18.31,1.01 37.82,1.01 38.51,1.7 43.41,1.7 43.86,1.25 44.12,1.25 v1(44.54,0.84)
  L06_SIG2 w0.119: v1(8.38,19.79) 8.05,20.12 8.05,23.56 8.81,24.33 v1(9.95,24.33)
  BOTTOM w0.14: J4.30 v1(9.95,24.33)
DM388_MCASP0_AXR3: length 64.5
  TOP w0.102: v1(45.23,0.93) 45.16,1 45.16,1.08 45.11,1.13 45.11,1.17 44.93,1.35 44.93,2.65 44.96,2.68 44.96,4.91 44.8,5.08 44.8,5.68 44.8,5.69 44.98,5.87 44.98,5.87 45.1,5.99 45.1,6.31 44.66,6.74 44.66,9.15 U7.AC31
  L03_SIG1 w0.119: v1(45.23,0.93) 44.92,1.24 44.92,1.25 44.65,1.53 43.97,1.53 43.52,1.98 38.4,1.98 37.7,1.27 19.02,1.27 18.68,1.6 18.61,1.6 16.46,3.75 v1(16.46,5.92)
  L06_SIG2 w0.119: v1(16.46,5.92) 16.02,6.36 16.02,19.8 14.89,20.93 14.38,20.93 12.87,22.44 12.87,23.89 v1(13.42,24.44)
  BOTTOM w0.14: J4.32 13.02,24.83 v1(13.42,24.44)
DM388_MCASP0_AXR4: length 62.9
  TOP w0.102: v1(44.93,12.19) 44.8,12.19 44.65,12.04 44.21,12.04 44.01,11.84 U7.AD26
  L03_SIG1 w0.102: v1(44.93,12.19) 44.14,12.19 43.84,11.89 43.84,9.83 42.02,8.01 42.02,8.01 41.8,7.79
  L03_SIG1 w0.119: 41.8,7.79 41.69,7.69 41.69,7.68 41.54,7.53 41.54,5.79 41.45,5.69 41.45,4.28 39.91,2.74 38.16,2.74 37.47,2.05 19.65,2.05 v1(18.24,3.46)
  L06_SIG2 w0.119: v1(13.44,25.63) 13.81,25.26 14.96,25.26 15.25,24.97 15.25,23.68 16.3,22.64 16.3,6.67 16.88,6.09 16.88,4.82 v1(18.24,3.46)
  BOTTOM w0.14: J4.36 11.4,26.2 12.25,26.2 12.29,26.16 12.91,26.16 v1(13.44,25.63)
DM388_MCASP0_AXR5: length 84
  TOP w0.102: v1(44.43,11.63) 44.14,11.34 U7.AD27
  L03_SIG1 w0.102: v1(44.43,11.63) 44.05,11.24 44.05,10.44 44.05,9.73 42.11,7.79
  L03_SIG1 w0.119: 42.11,7.79 41.91,7.6 41.91,5.77 41.8,5.66 41.8,4.13 40.19,2.52 38.25,2.52 37.51,1.78 19.2,1.78 17.69,3.29 17.69,4.02 v1(18,4.33)
  L06_SIG2 w0.119: v1(18,4.33) 18,4.84 18.08,4.92 18.08,6.13 16.84,7.37 16.84,24.12 15.8,25.15 15.8,25.62 14.77,26.66 13.44,26.66 11.95,28.15 11.95,33.69 12.87,34.61 13.34,34.61 14.28,35.55 14.28,36.17 14.83,36.72 15.09,36.72 15.38,37.01 15.38,37.07 16.38,38.07 20.43,38.07 20.78,37.72 v1(20.81,37.72)
  BOTTOM w0.14: J4.79 20.2,38.33 v1(20.81,37.72)
DM388_MCASP1_ACLKR: length 68
  L03_SIG1 w0.119: v1(66.83,20.19) 69,20.19 69.2,20.4 69.2,22.36 69.81,22.97 70.15,22.97 70.4,22.73 70.4,22.72 70.83,22.29 75.96,22.29 76.79,21.46 v1(77.58,21.46)
  L06_SIG2 w0.119: v1(77.58,21.46) 78.45,20.6 78.45,14.79 65.09,1.44 49.19,1.44 48.81,1.81 47.09,1.81 46.61,1.33 v1(46.61,0.89)
  BOTTOM w0.14: J5.21 65.4,21.77 66.76,20.4 66.76,20.27 v1(66.83,20.19) ; R138.1 42.61,3.7 43.08,3.23 43.2,3.23 44.47,1.96 46.22,1.96 46.61,1.57 v1(46.61,0.89)
DM388_MCASP1_ACLKX: length 60.1
  L06_SIG2 w0.119: v1(42.37,1.19) 43.64,2.46 49.08,2.46 49.45,2.08 58.37,2.08 59.54,3.25 65.99,3.25 77.8,15.06 77.8,17.84 75.5,20.14 74.44,20.14 74.03,19.73 v1(73.32,19.73)
  BOTTOM w0.102: R128.1 42.45,7.79
  BOTTOM w0.14: J3.81 v1(73.32,19.73) ; 42.45,7.79 42.45,7.12 41.79,6.46 41.79,5.93 41.33,5.47 41.33,4.04 40.55,3.27 40.55,1.71 40.91,1.35 42.2,1.35 v1(42.37,1.19)
DM388_MCASP1_AFSR: length 61.7
  TOP w0.102: v1(45.51,12.3) 45.48,12.32 45.34,12.32 45.09,12.57 44.77,12.57 44.76,12.57 44.65,12.57 44.48,12.73 U7.AC24
  TOP w0.14: v1(70.46,13.29) 72.17,11.58 72.17,7.85 65.39,1.07 v1(48.4,1.07)
  L03_SIG1 w0.102: v1(45.51,12.3) 45.51,11.86 45.51,11.86 45.51,10.12 44.28,8.89 43.77,8.89 42.67,7.79
  L03_SIG1 w0.119: v1(48.4,1.07) 48.09,1.38 48.09,1.62 47.02,2.69 44.48,2.69 42.08,5.1 42.08,5.55 42.19,5.66 42.19,7.31 42.67,7.79
  BOTTOM w0.14: v1(70.46,13.29) 69.43,13.29 68.82,13.9 68.82,14.21 68.36,14.67 68.36,16.13 65.94,18.54 65.94,18.96 65.89,19.01 65.89,19.03 64.65,20.27 J5.27
DM388_MCASP1_AFSX: length 64
  TOP w0.102: v1(45.52,12.85) 45.52,12.98 44.98,13.52 U7.AB22
  L03_SIG1 w0.102: 44.1,7.79 44.1,8.33 45.89,10.11 45.89,12.58 45.61,12.85 v1(45.52,12.85)
  L03_SIG1 w0.119: v1(74.68,18.85) 76.9,16.62 76.9,4.65 73.21,0.96 67.62,0.96 67.61,0.94 49.54,0.94 47.54,2.95 47.53,2.95 47.24,3.24 45.59,3.24 43.72,5.1 43.72,6.25 44.1,6.64 44.1,7.79
  BOTTOM w0.14: v1(74.68,18.85) 74.23,18.85 74.23,18.85 74.21,18.85 73.83,19.23 J3.83
DM388_MCASP1_AXR0: length 59
  TOP w0.102: v1(45.45,13.68) 45.62,13.84 U7.Y22
  L03_SIG1 w0.102: v1(45.45,13.68) 45.76,13.98 46.19,13.98 46.79,13.39 47.14,13.39 47.6,12.93 47.6,9.97 46.65,9.02 45.78,9.02 45.18,8.41 45.18,7.79
  L03_SIG1 w0.119: v1(73.32,18.73) 73.79,18.73 76.36,16.16 76.36,10.46 67.38,1.49 50.72,1.49 50.72,1.49 49.87,1.49 49.11,2.25 49.11,2.89 45.18,6.82 45.18,7.79
  BOTTOM w0.14: J3.85 v1(73.32,18.73)
DM388_MCASP1_AXR1: length 56.3
  TOP w0.102: v1(46.41,14.34) U7.Y21
  L03_SIG1 w0.102: v1(46.41,14.34) 47,14.34 47.8,13.54 47.8,9.89 46.7,8.79 46.15,8.79 45.5,8.13 45.5,7.79
  L03_SIG1 w0.119: v1(74.2,17.73) 76.04,15.89 76.04,10.98 66.88,1.82 50,1.82 49.38,2.44 49.38,3.01 45.5,6.9 45.5,7.79
  BOTTOM w0.14: J3.87 73.7,18.23 v1(74.2,17.73)
DM388_MDIO_CLK: length 26.6
  TOP w0.14: R65.1 39.44,28.33 39.13,28.02 34.3,28.02 v1(33.76,27.48)
  L06_SIG2 w0.119: v1(33.76,27.48) 33.41,27.84 30.87,27.84 30.18,27.15 28.66,27.15 28.48,26.97 28.13,26.97 26.85,28.26 26.56,28.26 26.12,27.82 26.12,27.42 25.62,26.92 18.43,26.92 18.33,27.02 18.21,27.02 v1(17.9,26.71)
  BOTTOM w0.14: J4.35 17.54,26.33 17.9,26.68 v1(17.9,26.71)
DM388_MDIO_DAT: length 36.7
  TOP w0.102: U7.AG3 42.01,23.34 v1(42,23.35)
  L03_SIG1 w0.102: v1(42,23.35) 42,25.08 40.49,26.59
  L03_SIG1 w0.119: v1(14.1,25.7) 14.52,25.29 14.96,25.29 15.37,25.69 16.96,25.69 17.33,25.33 18.47,25.33 18.71,25.57 29.55,25.57 29.64,25.48 30.21,25.48 30.27,25.55 30.78,25.55 32.49,27.26 33.1,27.26 33.96,26.39 37.34,26.39 38.19,27.24 38.71,27.24 38.8,27.14 39.94,27.14 40.49,26.59
  BOTTOM w0.14: J4.37 15.09,26.83 14.61,26.35 14.29,26.35 14.1,26.15 v1(14.1,25.7)
DM388_MMC0_CLK: length 105
  TOP w0.14: U3.20 v1(61.2,39.8)
  BOTTOM w0.14: v1(61.2,39.8) 59.9,39.8 58.33,41.36 58.33,42.66 58.33,42.66 58.33,45.05 59.11,45.83 72.07,45.83 72.36,45.83 79.07,39.11 79.07,37.29 78.29,36.5 78.29,32.21 79.07,31.42 79.07,12.42 78.39,11.73 78.39,2.62 76.53,0.76 49.47,0.76 48.39,1.85 48.39,1.89 47.22,3.05 45.21,3.05 45.11,3.15 R136.2
DM388_MMC0_CMD: length 94.8
  TOP w0.14: v1(59.39,41.07) 59.39,41.52 59.51,41.64 U3.18
  L06_SIG2 w0.119: v1(47.78,0.74) 47.84,0.68 65.45,0.68 79.09,14.33 79.09,21.9 78.72,22.27 78.72,37.77 73.07,43.42 63.11,43.42 60.76,41.07 v1(59.39,41.07)
  BOTTOM w0.102: 44.48,7.79 R126.2
  BOTTOM w0.14: v1(47.78,0.74) 47.78,1.45 46.59,2.64 44.98,2.64 44.48,3.14 44.48,5.16 45,5.68 45,6.3 44.79,6.52 44.79,7.36 44.48,7.67 44.48,7.79
DM388_MMC0_DAT0: length 93.4
  TOP w0.14: v1(58.99,42.04) 59.01,42.04 59.04,42.07 59.09,42.07 59.16,42.14 U3.17
  BOTTOM w0.14: RA12.4 46.19,4.2 46.99,3.4 47.55,3.4 48.73,2.23 48.73,1.99 49.62,1.1 67.27,1.1 78.73,12.56 78.73,31.28 77.94,32.07 77.94,36.64 78.73,37.43 78.73,38.97 72.21,45.49 72.01,45.49 59.26,45.49 58.67,44.9 58.67,42.81 58.99,42.49 v1(58.99,42.04)
DM388_MMC0_DAT1: length 90.7
  TOP w0.14: U3.16 v1(59.36,42.64)
  BOTTOM w0.14: v1(59.36,42.64) 58.96,43.05 58.96,44.41 58.91,44.45 58.91,44.8 59.36,45.25 72.11,45.25 78.49,38.87 78.49,37.53 77.7,36.74 77.7,31.97 78.49,31.18 78.49,12.66 67.17,1.34 49.72,1.34 48.97,2.09 48.97,2.42 47.71,3.68 47.25,3.68 46.69,4.24 RA12.3
DM388_MMC0_DAT2: length 88.4
  TOP w0.14: v1(59.34,44.63) 58.96,44.25 58.96,43.28 59.1,43.14 U3.15
  BOTTOM w0.14: RA12.2 47.19,4.27 47.27,4.2 47.27,4.19 47.43,4.03 47.44,4.03 47.53,3.94 47.87,3.94 49.21,2.59 49.21,2.19 49.82,1.58 67.07,1.58 78.25,12.76 78.25,31.08 77.46,31.87 77.46,36.84 78.25,37.63 78.25,38.7 71.99,44.96 60.12,44.96 59.79,44.63 v1(59.34,44.63)
DM388_MMC0_DAT3: length 85.1
  TOP w0.14: U3.14 v1(59.39,43.64)
  BOTTOM w0.14: RA12.1 47.69,4.45 49.45,2.69 49.45,2.29 49.92,1.82 66.97,1.82 78.01,12.86 78.01,30.98 77.22,31.77 77.22,36.94 78.01,37.73 78.01,38.53 71.87,44.66 61.66,44.66 60.64,43.64 v1(59.39,43.64)
DM388_MMC1_CLK: length 52.6
  L06_SIG2 w0.119: v1(77.58,20.17) 77.21,20.54 74.39,20.54 74.22,20.37 70.34,20.37 v1(69.98,20.02)
  BOTTOM w0.14: J3.80 69.32,20.23 69.53,20.02 v1(69.98,20.02) ; v1(77.58,20.17) 77.58,13.18 66.57,2.17 52.53,2.17 52.52,2.17 50.4,2.17 50.4,2.18 50.04,2.18 49.8,2.43 49.8,3.17 48.67,4.29 R135.1
DM388_MMC1_CMD: length 52
  L06_SIG2 w0.119: v1(77.07,17.15) 73.41,17.15 v1(70.68,19.88)
  BOTTOM w0.102: R125.1 47.95,8.4 48.25,8.1 48.25,7.79
  BOTTOM w0.14: v1(77.07,17.15) 77.07,13.15 66.69,2.77 56.66,2.77 56.34,3.09 50.6,3.09 49.26,4.43 49.26,6.22 48.52,6.96 48.52,7.37 48.25,7.63 48.25,7.79 ; J3.82 69.35,19.73 69.51,19.57 70.06,19.57 70.07,19.56 70.36,19.56 v1(70.68,19.88)
DM388_MMC1_DAT0: length 38.4
  L06_SIG2 w0.119: v1(69.24,19.23) 69.24,18.79 69.02,18.56 69.02,17.52 70.06,16.49 74.08,16.49 75.82,14.75 75.82,13.99 74.76,12.93 v1(74.01,12.93)
  BOTTOM w0.14: v1(74.01,12.93) 74.01,12.36 66.63,4.98 55.1,4.98 54.47,5.6 RA13.5 ; J3.84 v1(69.24,19.23)
DM388_MMC1_DAT1: length 35.8
  L03_SIG1 w0.119: v1(74.22,13.84) 74.22,15.96 71.01,19.18 v1(70.57,19.18)
  BOTTOM w0.14: v1(74.22,13.84) 74.54,13.53 74.54,12.48 66.74,4.67 54.9,4.67 54.47,5.1 RA13.6 ; v1(70.57,19.18) 69.88,19.18 69.71,19.01 69.6,18.96 69.42,18.84 69.3,18.73 J3.86
DM388_MMC1_DAT2: length 36
  L06_SIG2 w0.119: v1(74.98,13.74) 74.98,14.82 73.96,15.85 70.31,15.85 68.84,17.31 68.84,17.37 v1(68.53,17.68)
  BOTTOM w0.14: RA13.7 54.27,4.6 54.53,4.34 66.82,4.34 74.98,12.51 v1(74.98,13.74) ; J3.88 67.75,17.79 67.86,17.68 v1(68.53,17.68)
DM388_MMC1_DAT3: length 38.7
  L03_SIG1 w0.119: v1(75.4,14.58) 75.4,15.31 72.18,18.53 72.18,19.26 70.91,20.53 70.81,20.53 v1(69.62,21.73)
  BOTTOM w0.14: J3.76 v1(69.62,21.73) ; v1(75.4,14.58) 75.4,14.13 75.45,14.08 75.45,12.56 66.99,4.1 RA13.8
DM388_MMC1_DAT6/GP0_12: length 77.8
  TOP w0.102: v1(45.94,1.03) 45.93,1.04 45.8,1.04 45.75,1.09 45.67,1.09 45.32,1.44 45.19,1.58 45.19,2.55 45.22,2.58 45.22,5.02 45.05,5.18 45.05,5.58 45.24,5.76 45.24,5.77 45.36,5.89 45.36,6.41 44.98,6.79 U7.AB31
  L03_SIG1 w0.119: v1(17.67,5.09) 17.33,4.75 17.33,3.27 19.09,1.51 37.55,1.51 38.29,2.25 44.72,2.25 v1(45.94,1.03)
  L06_SIG2 w0.119: v1(13.44,35.3) 13.03,34.88 12.76,34.88 11.68,33.8 11.68,28.11 13.35,26.44 14.68,26.44 15.53,25.58 15.53,24.82 16.57,23.78 16.57,7.17 17.67,6.07 v1(17.67,5.09)
  BOTTOM w0.14: J4.70 13.42,35.33 v1(13.44,35.3)
DM388_MMC1_DAT7/GP0_13: length 74.2
  TOP w0.102: U7.AC30 44.2,9.56 44.2,9.13 44.41,8.92 44.41,6.63 44.56,6.48 v1(44.56,6.05)
  L06_SIG2 w0.102: 41.16,7.79 41.29,7.93 43.72,7.93 43.85,7.79
  L06_SIG2 w0.119: 41.16,7.79 40.56,7.19 40.56,6.85 38.91,5.2 38.91,4.33 37.15,2.57 21.74,2.57 18.93,5.39 18.93,6.75 17.11,8.57 17.11,24.31 16.04,25.38 16.04,26.45 14.92,27.57 13.34,27.57 12.22,28.69 12.22,33.57 12.99,34.34 13.4,34.34 14.4,35.33 v1(14.84,35.33) ; v1(44.56,6.05) 44.56,7.08 43.85,7.79
  BOTTOM w0.14: J4.72 14.34,35.83 v1(14.84,35.33)
DM388_MMC1_SDCD: length 40.7
  TOP w0.102: U7.G28 52.91,10.84 v1(52.94,10.86)
  L06_SIG2 w0.102: 56.01,7.79 v1(52.94,10.86)
  L06_SIG2 w0.119: v1(73.49,21.26) 73.14,20.91 70.01,20.91 69.92,20.83 69.89,20.83 67.92,18.86 67.92,17.43 71.54,13.81 71.54,10.32 67.93,6.71 66.77,6.71 66.12,6.06 65.42,6.06 64.62,6.86 56.94,6.86 56.01,7.79
  BOTTOM w0.14: v1(73.49,21.26) 73.49,21.51 73.27,21.73 J3.75
DM388_MMC2_CMD: length 17.7
  BOTTOM w0.102: J5.8 58.21,25.77 57.72,26.26 57.52,26.26
  BOTTOM w0.14: R105.2 43.27,27.11 43.93,26.45 46.4,26.45 46.6,26.65 48.5,26.65 48.73,26.88 53.43,26.88 54.05,26.26 57.52,26.26
DM388_MMC2_DAT0: length 17.7
  BOTTOM w0.102: J5.24 59.23,21.29 58.14,21.29 57.64,21.79 57.64,23.31 57.07,23.88 56.9,23.88 53.43,23.88 51.71,23.88 49.86,25.73 49.15,25.73 48.96,25.54 47.06,25.54 46.56,25.04 RA9.4
DM388_MMC2_DAT1: length 18.3
  BOTTOM w0.102: RA9.3 44.12,25.44 44.22,25.54 46.78,25.54 46.98,25.75 48.88,25.75 49.07,25.93 49.94,25.93 51.8,24.08 53.35,24.08 56.82,24.08 57.15,24.08 57.89,23.34 57.89,21.9 58.02,21.77 J5.22
DM388_MMC2_DAT2: length 22.1
  BOTTOM w0.102: J5.10 58.55,25.27 58.29,25.53 58.07,25.53 57.56,26.04 53.87,26.04 53.57,25.73 53.01,25.73 52.29,26.45 ; R115.2 43.67,22.74 43.4,23 42.86,23 42.64,23.23 42.64,25.84 43,26.21 43.8,26.21
  BOTTOM w0.14: 52.29,26.45 52.1,26.64 48.83,26.64 48.6,26.41 46.7,26.41 46.5,26.21 43.8,26.21
DM388_MMC2_DAT3: length 18.3
  TOP w0.14: v1(45.95,29.11) 45.47,29.59 43.41,29.59 43.31,29.49 RA1.2
  L06_SIG2 w0.119: v1(54.26,26.67) 54.21,26.71 53.75,26.71 53.68,26.79 52.44,26.79 49.86,29.37 46.65,29.37 46.39,29.11 v1(45.95,29.11)
  BOTTOM w0.14: J5.4 58.1,26.77 57.62,27.25 54.88,27.25 54.3,26.67 v1(54.26,26.67)
DM388_MMC2_DAT4: length 17.5
  TOP w0.14: RA1.1 44.26,29.03 v1(44.68,28.6)
  L06_SIG2 w0.119: v1(44.68,28.6) 44.99,28.91 44.99,28.94 45.65,29.59 49.95,29.59 52.31,27.23 53.23,27.23 53.35,27.11 54.45,27.11 v1(54.89,26.67)
  BOTTOM w0.102: 58.09,26.27 J5.6
  BOTTOM w0.14: v1(54.89,26.67) 55.34,26.67 55.47,26.8 57.56,26.8 58.09,26.27
DM388_MMC2_DAT5: length 26.3
  TOP w0.14: RA1.3 42.81,29.75 v1(44.73,31.67)
  L06_SIG2 w0.119: v1(54.97,28.07) 54.51,28.07 54.41,28.17 53.71,28.17 53,28.88 51.56,28.88 50.55,29.89 49.26,29.89 48.32,30.83 45.58,30.83 v1(44.73,31.67)
  BOTTOM w0.14: v1(54.97,28.07) 55.42,28.07 55.58,27.91 57.7,27.91 57.95,28.16 59.92,28.16 60.35,27.73 60.35,26.61 60.63,26.33 60.63,23.95 60.44,23.77 J5.14
DM388_MMC2_DAT6: length 28.3
  TOP w0.14: RA1.4 42.31,29.96 v1(44.02,31.67)
  L06_SIG2 w0.119: v1(44.02,31.67) 44.44,32.09 44.91,32.09 45.89,31.1 49.72,31.1 51.65,29.18 53.15,29.18 53.72,28.61 v1(54.29,28.61)
  BOTTOM w0.14: J5.16 60.67,23.27 60.87,23.46 60.87,26.43 60.59,26.71 60.59,27.83 59.87,28.55 57.94,28.55 57.62,28.23 56.08,28.23 55.7,28.61 54.75,28.61 54.75,28.61 v1(54.29,28.61)
DM388_MMC2_DAT7: length 20.1
  BOTTOM w0.102: 44.61,25.97 43.42,25.97 43.12,25.67 RA9.1 ; J5.18 58.47,22.77 58.37,22.87 58.37,23.57 58.07,23.88 58.03,23.88 56.64,25.27 56.58,25.27 56.58,25.27 56.41,25.27 56.41,25.27 55.37,25.27 54.61,24.51 52.27,24.51 51.69,25.09 51.69,25.93 51.29,26.34 48.87,26.34
  BOTTOM w0.14: 44.61,25.97 46.6,25.97 46.8,26.17 48.7,26.17 48.87,26.34
DM388_MMC2_DAT_0: length 2.2
  TOP w0.102: v1(44.93,22.63) 44.72,22.84 U7.AC4
  BOTTOM w0.102: RA9.5 44.62,23.66 44.45,23.5 44.45,23.11 v1(44.93,22.63)
DM388_MMC2_DAT_1: length 2.9
  TOP w0.102: v1(44.92,22.05) 44.64,22.34 U7.AC5
  BOTTOM w0.102: RA9.6 44.12,23.12 44.55,22.69 44.55,22.43 v1(44.92,22.05)
DM388_MMC2_DAT_3: length 4
  TOP w0.102: U7.AD1 43.98,24.91 43.72,25.17 43.72,26.59
  TOP w0.14: 43.72,26.59 43.46,26.85 43.46,27.34 43.31,27.5 RA1.7
DM388_MMC2_DAT_4: length 4.5
  TOP w0.102: 44,26.59 44,26.47 44,25.18 44.18,25 44.18,24.99 44.26,24.91 44.26,24.12 U7.AD2
  TOP w0.14: 44,26.59 44,26.72 44,26.76 43.77,27 43.77,27.04 43.76,27.05 43.76,27.45 43.81,27.5 RA1.8
DM388_MMC2_DAT_5: length 4
  TOP w0.102: U7.AE1 43.48,26.42 43.3,26.59
  TOP w0.14: RA1.6 42.81,27.5 43.17,27.13 43.17,26.73 43.3,26.59
DM388_MMC2_DAT_6: length 4.7
  TOP w0.102: 42.88,26.59 43.18,26.29 43.18,25.97 43.21,25.94 43.21,24.74 43.2,24.73 43.2,24.12 U7.AE2
  TOP w0.14: 42.88,26.59 42.88,27.01 42.31,27.58 RA1.5
DM388_MMC2_DAT_7: length 1.2
  TOP w0.102: U7.AE3 43.06,23.34 v1(43.02,23.38)
  BOTTOM w0.102: v1(43.02,23.38) 43.12,23.49 RA9.8
DM388_MMC2_S_CLK: length 3.9
  TOP w0.102: v1(44.92,21.48) 44.56,21.84 U7.AC6
  BOTTOM w0.102: v1(44.92,21.48) 44.9,21.46 44.54,21.46 44.35,21.66 44.35,22.61 43.92,23.03 43.92,23.04 43.62,23.34 RA9.7
DM388_MMC2_SCLK: length 19.2
  BOTTOM w0.102: J5.20 58.28,22.27 58.15,22.4 58.15,23.42 56.49,25.07 55.45,25.07 54.67,24.28 53.26,24.28 51.88,24.28 50.03,26.14 48.98,26.14 48.79,25.95 46.9,25.95 46.69,25.75 43.82,25.75 43.62,25.55 RA9.2
DM388_MUX_SEL: length 15.1
  TOP w0.102: 51.85,26.79 51.85,25.96 51.14,25.26 50.61,25.26 50.32,24.97 50.11,24.97 U7.N1
  TOP w0.14: U4.1 52.31,35.26 52.27,35.22 R53.1 52.96,34.67 53.56,34.07 53.56,33.95 53.59,33.92 53.59,33.45 53.25,33.12 52.81,33.12 52.37,32.68 52.37,30.89 51.85,30.37 51.85,26.79
DM388_PCIE_RXN0: length 52.5
  TOP w0.102: U7.J30 51.48,8.1 51.74,7.84 51.74,7.42 51.88,7.28 51.88,6.47 51.99,6.36 v1(52.06,6.36)
  L03_SIG1 w0.102: v1(65.88,27.83) 65.61,27.56 65.61,27.46 65.28,27.13 64.85,27.13 63.11,25.38 63.11,17.14 64.85,15.39 67.17,15.39 67.66,14.91 70.07,14.91 71.33,13.65 71.33,10.43 67.83,6.94 52.08,6.94 51.87,6.72 51.87,6.55 v1(52.06,6.36)
  BOTTOM w0.102: J5.3 64.08,26.85 64.55,26.85 64.73,27.03 64.84,27.03 64.94,27.13 65.19,27.13 65.54,27.47 65.54,27.49 v1(65.88,27.83)
DM388_PCIE_RXP0: length 52.5
  TOP w0.102: v1(51.35,6.36) 51.42,6.36 51.6,6.53 51.6,7.17 51.46,7.31 51.46,7.83 51.27,8.02 51.27,9.51 50.98,9.81 U7.K30
  L03_SIG1 w0.102: v1(51.35,6.36) 51.54,6.55 51.54,6.86 51.95,7.27 67.69,7.27 71,10.57 71,13.51 69.93,14.58 67.52,14.58 67.04,15.06 64.71,15.06 62.78,17 62.78,25.52 64.71,27.46 65.15,27.46 65.26,27.58 65.26,27.78 65.16,27.88 64.97,27.88 v1(64.91,27.83)
  BOTTOM w0.102: v1(64.91,27.83) 65.14,27.83 65.26,27.71 65.26,27.59 65.08,27.41 64.82,27.41 64.72,27.31 64.61,27.31 64.49,27.19 64.08,27.19 J5.1
DM388_PCIE_TXN0: length 50.9
  TOP w0.102: C64.2 50.85,3.35 50.85,2.93 51.18,2.61 v1(51.18,2.6)
  L03_SIG1 w0.102: v1(51.18,2.6) 51.18,2.61 50.89,2.9 50.89,3.04 52.96,5.11 67.5,5.11 72.29,9.9 72.29,13.96 70.47,15.77 68.18,15.77 64.11,19.84 64.11,24.6 64.73,25.22 65.21,25.22 65.61,25.63 65.61,26.06 v1(65.88,26.33)
  BOTTOM w0.102: J5.9 64.67,25.27 64.78,25.38 65.27,25.38 65.56,25.67 65.56,26.01 v1(65.88,26.33)
DM388_PCIE_TXP0: length 50.8
  TOP w0.102: C63.2 50.28,3.7 50.55,3.43 50.55,2.93 v1(50.22,2.61)
  L03_SIG1 w0.102: v1(50.22,2.61) 50.56,2.95 50.56,3.17 52.83,5.44 67.36,5.44 71.96,10.03 71.96,13.82 70.34,15.44 68.04,15.44 63.78,19.7 63.78,24.74 64.6,25.55 65.07,25.55 65.28,25.77 65.28,26.23 65.18,26.33 v1(64.91,26.33)
  BOTTOM w0.102: v1(64.91,26.33) 65.18,26.33 65.28,26.23 65.28,25.78 65.15,25.66 64.78,25.66 64.67,25.77 J5.7
DM388_PMIC_PWRON: length 65.6
  TOP w0.102: U1.E4 v1(32.91,50.24)
  L06_SIG2 w0.102: 28.45,50.17 28.83,49.78 32.46,49.78 v1(32.91,50.24)
  L06_SIG2 w0.119: v1(13.67,17.96) 13.36,17.65 13.22,17.65 13.21,17.66 12.96,17.66 12.85,17.78 9.34,17.78 7.5,19.62 7.5,26.14 8.55,27.2 8.55,42.26 12.37,46.08 12.37,47.42 14.71,49.75 24.89,49.75 25.81,50.67 27.94,50.67 28.45,50.17
  BOTTOM w0.102: v1(32.91,50.24) 33.13,50.46 33.6,50.93 33.81,50.93 34.16,51.28 34.49,51.28 34.71,51.5 35.17,51.96 R94.2
  BOTTOM w0.14: J4.10 13.05,18.83 13.44,18.43 13.44,18.19 v1(13.67,17.96)
DM388_PORN: length 7.3
  TOP w0.102: 42.14,7.79 42.14,7.95 42.27,8.08 42.27,9.55 U7.AH30
  TOP w0.14: 42.14,7.79 42.14,5.63 42.07,5.56 42.07,5.2 42.25,5.02 42.5,5.02 42.72,4.8 U11.4 43.19,4.28 43.22,4.3 R83.1
DM388_RSTOUT: length 60
  TOP w0.102: 40.89,7.79 41.2,8.09 41.2,9.56 U7.AJ30
  TOP w0.14: v1(39.63,6.88) 39.97,7.22 R81.1 40.33,7.22 40.89,7.79
  L06_SIG2 w0.102: 57.31,17.58 56.43,17.58 55.27,16.42 55.27,16 54.64,15.37 54.43,15.37 53.92,14.86 52.35,14.86 51.76,15.45 50.75,15.45 50.03,14.73 48.59,14.73 47.98,14.12 47.98,12.77 47.61,12.39 47.61,9.74 49.28,8.08 49.67,8.08 49.96,7.79 ; 40.53,7.79 40.87,8.13 44.18,8.13 44.52,7.79
  L06_SIG2 w0.119: 49.96,7.79 50.83,6.92 50.83,5.84 50.48,5.49 46.82,5.49 44.52,7.79 ; v1(70.07,29.17) 69.66,28.76 69.55,28.76 66.47,25.68 65.94,25.68 64.32,25.68 63.53,24.89 61.95,24.89 60.28,23.23 60.28,20.56 57.31,17.58 ; 40.53,7.79 v1(39.63,6.88)
  BOTTOM w0.14: v1(70.07,29.17) 69.63,28.73 J3.50
DM388_RTCK: length 61.8
  L06_SIG2 w0.119: v1(69.36,31.23) 69.79,31.23 70.21,31.65 71.84,31.65 72.03,31.45 74.17,31.45 74.41,31.22 74.81,31.22 74.81,31.22 75.14,31.22 75.14,31.22 75.67,31.22 v1(76.71,30.18)
  BOTTOM w0.102: R124.2 49.05,7.79
  BOTTOM w0.14: 49.05,7.79 49.05,7.11 49.74,6.42 49.74,6.27 49.74,5.33 51.4,3.68 54.11,3.68 54.24,3.81 67.04,3.81 76.09,12.86 76.09,17.63 76.92,18.45 76.92,22.85 77.05,22.99 77.05,29.81 77.03,29.83 77.03,29.86 v1(76.71,30.18) ; J3.40 v1(69.36,31.23)
DM388_SERDES_CLKN: length 46.3
  TOP w0.102: C66.2 52.99,3.32 52.99,2.77 53.1,2.66 v1(53.37,2.66)
  L03_SIG1 w0.102: v1(65.48,23.16) 65.25,23.39 65.13,23.39 65.03,23.29 65.03,22.21 65.49,21.74 65.49,19.71 68.57,16.64 70.91,16.64 73.26,14.29 73.26,9.31 67.98,4.04 53.63,4.04 52.94,3.34 52.94,2.76 53.04,2.66 v1(53.37,2.66)
  BOTTOM w0.102: J5.15 64.67,23.27 64.78,23.38 65.27,23.38 v1(65.48,23.16)
DM388_SERDES_CLKP: length 46.4
  TOP w0.102: v1(52.41,2.66) 52.71,2.96 52.71,3.35 C65.2
  L03_SIG1 w0.102: v1(65.48,23.87) 65.33,23.72 64.99,23.72 64.7,23.43 64.7,22.07 65.16,21.6 65.16,19.58 68.43,16.31 70.77,16.31 72.93,14.15 72.93,9.45 67.85,4.37 53.5,4.37 52.61,3.48 52.61,2.86 v1(52.41,2.66)
  BOTTOM w0.102: J5.13 64.67,23.77 64.78,23.66 65.27,23.66 v1(65.48,23.87)
DM388_SPI0_SCS[0]N: length 43.8
  TOP w0.102: U7.G29 52.89,10.34 v1(52.94,10.29)
  L06_SIG2 w0.119: v1(58.02,8.48) 58.33,8.8 58.91,8.8 59.3,8.41 59.89,8.41 60.76,7.54 67.82,7.54 70.88,10.6 70.88,13.46 69.48,14.85 69.23,14.85 67.03,17.06 67.03,19.14 68.25,20.35 68.25,20.95 69.47,22.17 70.48,22.17 v1(71.01,21.64)
  BOTTOM w0.102: v1(52.94,10.29) 53.39,10.29 53.5,10.4 53.5,11.19 53.81,11.51 56.32,11.51 56.88,10.95 57,10.95
  BOTTOM w0.14: J3.70 69.65,23.23 69.65,23.23 69.82,23.23 69.83,23.23 70.17,23.23 71.01,22.39 v1(71.01,21.64) ; 57,10.95 58.02,9.93 v1(58.02,8.48)
DM388_SPI1_D[0]: length 15.1
  TOP w0.102: v1(49.91,13.36) 49.88,13.34 U7.N23
  L03_SIG1 w0.102: v1(49.91,13.36) 49.91,13.5 50.2,13.79 51.04,13.79 51.54,13.29 53.2,13.29 54.16,12.32 57.26,12.32 57.28,12.34 57.31,12.34
  L03_SIG1 w0.119: 57.31,12.34 57.65,12.34 59.23,10.77 60.66,10.77 v1(60.99,11.1)
  BOTTOM w0.14: v1(60.99,11.1) 60.66,10.77 J5.62
DM388_SPI1_D[1]: length 38
  TOP w0.102: U7.M27 50.07,11.34 v1(50.5,10.91)
  L06_SIG2 w0.102: v1(50.5,10.91) 50.07,10.91 49.94,10.77 49.94,9.98 50.13,9.8 51.84,9.8 52.1,10.06 52.1,11.71 52.73,12.35 53.71,12.35 53.94,12.12 54.92,12.12 56.34,10.69 57,10.69 57.31,10.39
  L06_SIG2 w0.119: v1(69.65,12.78) 68.37,11.51 67.77,11.51 64.42,8.15 60.91,8.15 60.11,8.96 60.11,9.52 59.36,10.26 57.43,10.26 57.31,10.39
  BOTTOM w0.14: v1(69.65,12.78) 69.05,12.78 68,13.83 68,15.95 65.7,18.25 65.7,18.86 64.95,19.61 64.87,19.61 64.72,19.77 J5.29
DM388_SPI1_SCLK: length 29.2
  TOP w0.14: v1(60.76,6.2) 62.11,6.2 65.02,9.11 65.85,9.11 66.06,9.11 66.55,9.6 66.55,11.02 67.68,12.15 67.68,12.15 67.81,12.28 68.14,12.28 v1(68.46,12.6)
  BOTTOM w0.102: R123.2 52.72,8.48 53.41,7.79
  BOTTOM w0.14: v1(60.76,6.2) 55.26,6.2 54.74,6.71 54.49,6.71 53.41,7.79 ; v1(68.46,12.6) 67.26,13.79 67.26,16.2 65.36,18.1 65.36,18.71 64.8,19.27 J5.31
DM388_SPI1_SCS[0]N: length 21.2
  TOP w0.102: U7.J29 51.12,10.34 v1(51.03,10.44)
  L06_SIG2 w0.102: 57.31,10.75 57.13,10.92 56.47,10.92 55.07,12.32 54.02,12.32 53.72,12.62 52.66,12.62 51.77,11.74 51.77,11.18 v1(51.03,10.44)
  L06_SIG2 w0.119: v1(65.7,10.27) 65.43,10 65.43,9.86 64.01,8.43 61.07,8.43 60.38,9.12 60.38,9.63 59.48,10.53 57.52,10.53 57.31,10.75
  BOTTOM w0.14: J5.61 64.72,10.77 64.72,10.77 65.2,10.77 v1(65.7,10.27)
DM388_SPI[0]_D[0]: length 34.1
  TOP w0.102: v1(51.05,11.05) 51.26,10.84 U7.J28
  L06_SIG2 w0.102: 57.31,11.18 57.17,11.18 57.13,11.13 56.59,11.13 55.2,12.52 54.11,12.52 53.8,12.83 52.57,12.83 51.41,11.67 51.41,11.41 v1(51.05,11.05)
  L06_SIG2 w0.119: v1(69.98,22.56) 69.47,22.56 67.98,21.06 67.98,20.53 66.76,19.31 66.76,16.81 67.73,15.84 67.73,12.66 67,11.93 64.26,11.93 62.99,10.66 60.16,10.66 59.64,11.18 57.31,11.18
  BOTTOM w0.14: v1(69.98,22.56) 69.53,22.56 69.36,22.73 J3.72
DM388_SPI[0]_D[1]: length 41.1
  TOP w0.102: U7.J27 51.32,11.34 v1(51.03,11.63)
  L06_SIG2 w0.119: v1(70.24,21.78) 69.93,21.46 69.91,21.46 69.78,21.34 69.57,21.34 67.48,19.24 67.48,17.17 71.1,13.55 71.1,10.51 67.91,7.32 60.4,7.32 v1(59.79,7.92)
  BOTTOM w0.102: v1(51.03,11.63) 52.16,11.63 52.29,11.5 53.52,11.5 53.73,11.71 56.44,11.71 56.68,11.47 56.68,11.44 56.9,11.22 57.21,11.22
  BOTTOM w0.14: v1(70.24,21.78) 69.92,22.09 69.83,22.09 69.7,22.23 J3.74 ; 57.21,11.22 58.35,10.08 58.35,9.27 59.38,8.24 59.47,8.24 v1(59.79,7.92)
